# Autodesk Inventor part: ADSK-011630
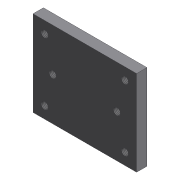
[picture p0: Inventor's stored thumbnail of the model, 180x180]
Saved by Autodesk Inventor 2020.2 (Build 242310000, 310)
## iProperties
Created: 2000-02
Part Number: ADSK-011630
Material: Pearson HRS
Document SubType Name: Modeling
Designer: sspink
Density: 7.83 g/cm^3
Appearance: Métal - Acier
Mass: 629.672 g
Surface Area: 209.865 cm^2
Volume: 80.4179 cm^3
Control State: 0
Master: False
Checked Out: False
Shininess: 0.0
Length Units: 11269
Angle Units: 11279
Time Units: 11290
Mass Units: 11283
Length Display Precision: 3
Angle Display Precision: 2
Compacted: True
Cutlength: 3.25
Material Desc: FLAT,HRS,0.38 X 4.00
Material_Number: A084411
Dimensions: 82,5x10x100 mm
Mass: 0,63 kg
VLT_Material: Pearson HRS
Density: 0.0
Volumn: 0.0
Area: 0.0
PropertySet Name: Model Information
Author: sspink
Revision Number: -
Title: ADSK-011630
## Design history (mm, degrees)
sketch "Sketch2"
  geometry: L1 (38.75, 30)-(-38.75, 30); L2 (-38.75, 30)-(-38.75, -30); L3 (-38.75, -30)-(38.75, -30); L4 (38.75, -30)-(38.75, 30); 5 further points
  constraints: 8 end point, 3 vertical alignment, 2 coincident, 2 midpoint, 2 parallel, 1 horizontal, 1 horizontal alignment, 1 perpendicular
  dimensions: "d26" = 60 distance of L3.end L1.start; "d27" = 77.5 distance of L1.start L1.end
node "Hole1" dims "d14" = 6.647, "d15" = 9.525, "d16" = 6.35, "d17" = 60 deg, "d18" = 19.05, "d19" = 118 deg, "d28" = 16
sketch "Sketch3"
  geometry: L1 (31, 0)-(-31, 0); 4 further points
  constraints: 3 coincident, 2 end point, 1 horizontal, 1 midpoint
  dimensions: "d29" = 62 distance of L1.start L1.end
node "Hole2" dims "d20" = 6.647, "d21" = 9.525, "d22" = 6.35, "d23" = 60 deg, "d24" = 19.05, "d25" = 118 deg, "d30" = 16
node "Solide1"
  node "Extrusion1" dims "d2" = 10, "d3" = 0
sketch "Sketch1"
  geometry: L1 (-50, -41.25)-(50, -41.25); L2 (50, -41.25)-(50, 41.25); L3 (50, 41.25)-(-50, 41.25); L4 (-50, 41.25)-(-50, -41.25); 3 further points
  constraints: 8 end point, 2 midpoint, 2 parallel, 1 horizontal, 1 horizontal alignment, 1 perpendicular, 1 vertical alignment
  dimensions: "d0" = 100 distance between parallel lines of L2 L4; "d1" = 82.5 distance between parallel lines of L3 L1
node "Corps solides"
node "Corps surfaciques"
